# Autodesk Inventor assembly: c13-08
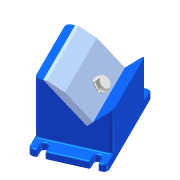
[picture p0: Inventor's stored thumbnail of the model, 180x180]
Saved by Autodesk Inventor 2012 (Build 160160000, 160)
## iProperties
Created: 2010-11
Part Number: c13-08
Document SubType Name: Assembly
Designer: Beta-8540w
Author: Beta-8540w
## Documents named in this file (5)
- C:\Users\VMuser\Desktop\Inventor 2012 Essentials\Assemblies\Chapter 13\c13-08.iam
- C:\Users\VMuser\Desktop\Inventor 2012 Essentials\Content Center Files\en-US\ISO 4017\ISO 4017 - M10 x 35ISO.ipt
- C:\Users\VMuser\Desktop\Inventor 2012 Essentials\Parts\Chapter 13\c13-02.ipt
- C:\Users\VMuser\Desktop\Inventor 2012 Essentials\Content Center Files\en-US\ISO 7091\ISO 7091 - ST 10 - 100 HV.ipt
- C:\Users\VMuser\Desktop\Inventor 2012 Essentials\Parts\Chapter 13\c13-01.ipt
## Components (4 placed, 4 different names)
1. c13-01:1 — Insert:1, Angle:1
2. c13-02:1 — Insert:1, Angle:1, Insert:2
3. ISO 4017 M10 x 35:1 — Insert:3, Bolt Angle
4. ISO 7091 ST 10 - 100 HV:1 — Insert:2, Insert:3
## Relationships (5: Insert 3, Angle 2)
- Insert:1: c13-01:1 ↔ c13-02:1
- Angle:1: c13-01:1 ↔ c13-02:1
- Insert:2: c13-02:1 ↔ ISO 7091 ST 10 - 100 HV:1
- Insert:3: ISO 4017 M10 x 35:1 ↔ ISO 7091 ST 10 - 100 HV:1
- Bolt Angle [Angle]: ISO 4017 M10 x 35:1
